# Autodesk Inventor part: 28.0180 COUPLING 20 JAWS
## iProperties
Created: 2007-06
Part Number: 28.0180 COUPLING 20 JAWS
Material: Steel
Document SubType Name: Modeling
Designer: Andy Moles
Mass: 427.752 g
Surface Area: 137.932 cm^2
Volume: 54.4907 cm^3
Density: 7.85 g/cm^3
Author: Andy Moles
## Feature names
1. Base1
